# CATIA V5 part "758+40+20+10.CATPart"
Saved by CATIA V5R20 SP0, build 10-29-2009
Part number: 758+40+20+10
Revision: TUTTO
Definition: NON CONOSCIUTO
Nomenclature: 758+40+20+10
Source: Unknown
Bounding box of the stored display mesh (mm): x -20 to 20, y 0 to 20, z -20 to 20
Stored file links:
  C:\Users\Utente\Desktop\IO LAVORO\3D X SITO CF\X 3D SITO CF 27-09-2020\758\758+40+20+10.CATPart
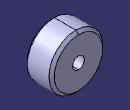
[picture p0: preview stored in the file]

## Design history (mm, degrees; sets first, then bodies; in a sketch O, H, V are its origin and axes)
Body1 "Importato1" (main body)
  Solid1: solid without history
